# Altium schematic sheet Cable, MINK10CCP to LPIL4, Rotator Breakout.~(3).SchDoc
size B; Organization: Monterey Bay Aquarium Research Institute; Address1: 7700 Sandholdt Rd; Address2: Moss Landing, CA 95039-9644; CompanyName: MBARI
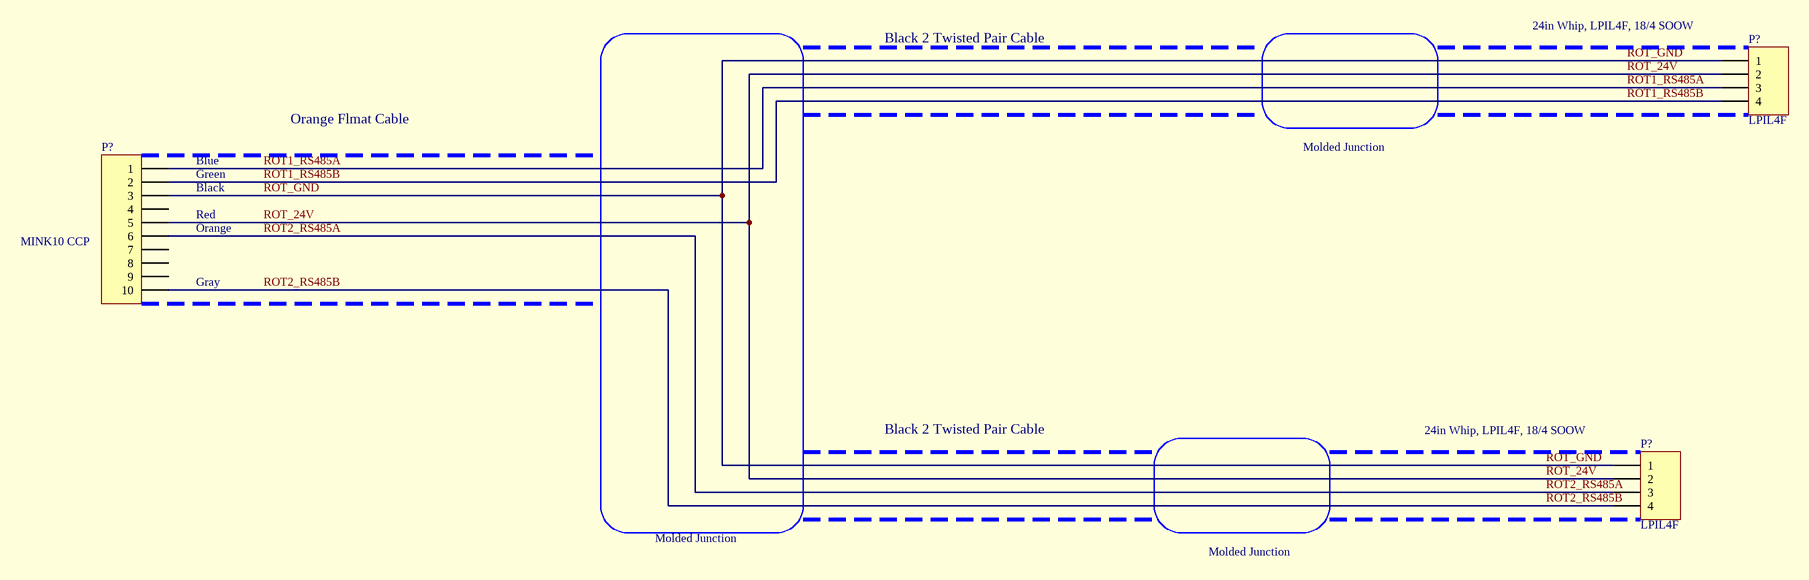
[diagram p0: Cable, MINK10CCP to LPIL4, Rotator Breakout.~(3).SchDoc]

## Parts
(Parts that share a designator on the sheet are numbered #1, #2 ... from top to bottom, then left to right.)
P?#1  LPIL4F  [HDR1X4]
P?#2  MINK10 CCP  [HDR1X10]
P?#3  LPIL4F  [HDR1X4]

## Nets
ROT1_RS485A: P?#1.3 P?#2.1
ROT1_RS485B: P?#1.4 P?#2.2
ROT2_RS485A: P?#2.6 P?#3.3
ROT2_RS485B: P?#2.10 P?#3.4
ROT_24V: P?#1.2 P?#2.5 P?#3.2
ROT_GND: P?#1.1 P?#2.3 P?#3.1

Not connected (* = marked no-connect by the designer): P?#2 4 7 8 9

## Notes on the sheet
- Black 2 Twisted Pair Cable
- (near P?#1) 24in Whip, LPIL4F, 18/4 SOOW
- Orange Flmat Cable
- Blue
- Green
- Black
- Molded Junction
- Red
- Orange
- Gray
- (near P?#3) 24in Whip, LPIL4F, 18/4 SOOW

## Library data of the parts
P?#1 P?#3 = Header 4: Header, 4-Pin
P?#2 = Header 10: Header, 10-Pin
